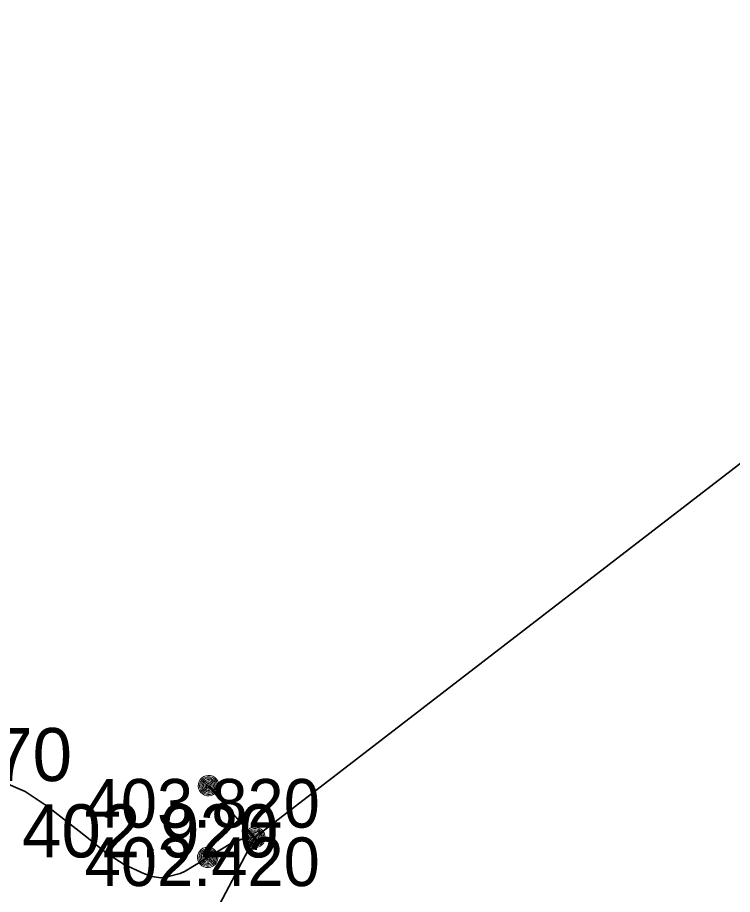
# Model space of a CAD drawing. Extents: x -873619 to -867639, y -1015082 to -1012326.
# Drawn here: x -867971.06 to -867954.89, y -1012799.51 to -1012779.69 of the extents above; entities that cross this region are included whole.
import ezdxf

# ---------------------------------------------------------------- set-up
doc = ezdxf.new("R2010")
doc.units = 0
doc.header["$LTSCALE"] = 0.44
for name, color, linetype, lineweight in [('1', 7, 'Continuous', 13), ('21', 7, 'Continuous', 35), ('23', 7, 'Continuous', 25), ('25', 7, 'Continuous', 13), ('32', 7, 'Continuous', 13)]:
    doc.layers.add(name, color=color, linetype=linetype, lineweight=lineweight)

msp = doc.modelspace()

# ---------------------------------------------------------------- linework, layer by layer
at = {"layer": '1'}
for points in [[(-867966.527, -1012798.672), (-867966.533, -1012798.62), (-867966.55, -1012798.57), (-867966.579, -1012798.526), (-867966.616, -1012798.489), (-867966.661, -1012798.462), (-867966.711, -1012798.445), (-867966.764, -1012798.441), (-867966.816, -1012798.448), (-867966.865, -1012798.467), (-867966.908, -1012798.496), (-867966.944, -1012798.535), (-867966.97, -1012798.58), (-867966.986, -1012798.631), (-867966.989, -1012798.683), (-867966.981, -1012798.735), (-867966.961, -1012798.784), (-867966.93, -1012798.827), (-867966.891, -1012798.861), (-867966.845, -1012798.887), (-867966.794, -1012798.901), (-867966.741, -1012798.903), (-867966.69, -1012798.893), (-867966.642, -1012798.872), (-867966.599, -1012798.841), (-867966.565, -1012798.8), (-867966.541, -1012798.754), (-867966.529, -1012798.703)], [(-867966.557, -1012798.672), (-867966.563, -1012798.623), (-867966.58, -1012798.577), (-867966.608, -1012798.537), (-867966.645, -1012798.505), (-867966.689, -1012798.483), (-867966.737, -1012798.472), (-867966.786, -1012798.472), (-867966.833, -1012798.485), (-867966.876, -1012798.509), (-867966.912, -1012798.542), (-867966.939, -1012798.583), (-867966.955, -1012798.63), (-867966.959, -1012798.679), (-867966.952, -1012798.727), (-867966.933, -1012798.772), (-867966.903, -1012798.812), (-867966.865, -1012798.843), (-867966.821, -1012798.863), (-867966.773, -1012798.873), (-867966.724, -1012798.871), (-867966.677, -1012798.856), (-867966.634, -1012798.831), (-867966.6, -1012798.797), (-867966.574, -1012798.755), (-867966.56, -1012798.708)], [(-867966.587, -1012798.672), (-867966.593, -1012798.627), (-867966.61, -1012798.585), (-867966.638, -1012798.55), (-867966.674, -1012798.523), (-867966.716, -1012798.506), (-867966.761, -1012798.501), (-867966.806, -1012798.507), (-867966.847, -1012798.526), (-867966.882, -1012798.554), (-867966.909, -1012798.591), (-867966.925, -1012798.633), (-867966.929, -1012798.678), (-867966.922, -1012798.723), (-867966.903, -1012798.764), (-867966.874, -1012798.798), (-867966.837, -1012798.824), (-867966.794, -1012798.84), (-867966.749, -1012798.843), (-867966.704, -1012798.835), (-867966.664, -1012798.815), (-867966.63, -1012798.786), (-867966.604, -1012798.748), (-867966.59, -1012798.705)], [(-867966.617, -1012798.672), (-867966.622, -1012798.631), (-867966.64, -1012798.594), (-867966.667, -1012798.563), (-867966.702, -1012798.542), (-867966.742, -1012798.531), (-867966.783, -1012798.533), (-867966.822, -1012798.546), (-867966.856, -1012798.57), (-867966.881, -1012798.602), (-867966.896, -1012798.64), (-867966.899, -1012798.681), (-867966.891, -1012798.721), (-867966.871, -1012798.757), (-867966.842, -1012798.786), (-867966.805, -1012798.805), (-867966.765, -1012798.813), (-867966.724, -1012798.809), (-867966.686, -1012798.794), (-867966.654, -1012798.768), (-867966.631, -1012798.734), (-867966.618, -1012798.695)], [(-867966.647, -1012798.672), (-867966.652, -1012798.636), (-867966.67, -1012798.604), (-867966.696, -1012798.579), (-867966.73, -1012798.564), (-867966.766, -1012798.561), (-867966.801, -1012798.569), (-867966.832, -1012798.589), (-867966.855, -1012798.617), (-867966.868, -1012798.651), (-867966.868, -1012798.688), (-867966.857, -1012798.723), (-867966.836, -1012798.752), (-867966.806, -1012798.773), (-867966.771, -1012798.783), (-867966.734, -1012798.781), (-867966.7, -1012798.767), (-867966.673, -1012798.744), (-867966.654, -1012798.712), (-867966.647, -1012798.677)], [(-867966.677, -1012798.672), (-867966.682, -1012798.641), (-867966.699, -1012798.615), (-867966.725, -1012798.598), (-867966.755, -1012798.591), (-867966.786, -1012798.595), (-867966.813, -1012798.612), (-867966.831, -1012798.636), (-867966.839, -1012798.667), (-867966.835, -1012798.697), (-867966.82, -1012798.725), (-867966.796, -1012798.744), (-867966.766, -1012798.753), (-867966.735, -1012798.75), (-867966.707, -1012798.736), (-867966.687, -1012798.712), (-867966.677, -1012798.683)], [(-867966.707, -1012798.672), (-867966.712, -1012798.648), (-867966.729, -1012798.63), (-867966.752, -1012798.621), (-867966.776, -1012798.624), (-867966.797, -1012798.638), (-867966.808, -1012798.66), (-867966.808, -1012798.685), (-867966.796, -1012798.706), (-867966.776, -1012798.72), (-867966.751, -1012798.723), (-867966.728, -1012798.714), (-867966.712, -1012798.696)], [(-867966.737, -1012798.672), (-867966.742, -1012798.657), (-867966.757, -1012798.651), (-867966.772, -1012798.655), (-867966.779, -1012798.669), (-867966.775, -1012798.684), (-867966.762, -1012798.693), (-867966.747, -1012798.69), (-867966.737, -1012798.678)]]:
    msp.add_lwpolyline(points, close=True, dxfattribs=at)
at = {"layer": '21'}
msp.add_line((-867966.775, -1012797.04), (-867965.676, -1012798.237), dxfattribs=at)
for points in [[(-867965.69, -1012798.22), (-867951.608, -1012787.375), (-867932.702, -1012789.133), (-867922.911, -1012779.695)], [(-867971.426, -1012796.948), (-867970.889, -1012797.18), (-867970.387, -1012797.515), (-867969.494, -1012798.212), (-867969.047, -1012798.575), (-867968.649, -1012798.834), (-867968.188, -1012799.044), (-867968.014, -1012799.106), (-867967.827, -1012799.134), (-867967.643, -1012799.106), (-867967.379, -1012799.036), (-867967.269, -1012798.98), (-867966.197, -1012798.333), (-867965.963, -1012798.255), (-867965.69, -1012798.22)], [(-868020.287, -1012856.898), (-867997.903, -1012847.584), (-867988.318, -1012833.474), (-867978.718, -1012822.899), (-867965.69, -1012798.22), (-867965.665, -1012798.299)]]:
    msp.add_lwpolyline(points, dxfattribs=at)
at = {"layer": '23'}
msp.add_line((-867966.74, -1012797.05), (-867965.665, -1012798.299), dxfattribs=at)
at = {"layer": '25'}
for points in [[(-867966.509, -1012797.05), (-867966.515, -1012796.998), (-867966.532, -1012796.948), (-867966.561, -1012796.904), (-867966.598, -1012796.867), (-867966.643, -1012796.84), (-867966.693, -1012796.823), (-867966.746, -1012796.819), (-867966.798, -1012796.826), (-867966.847, -1012796.845), (-867966.89, -1012796.874), (-867966.926, -1012796.913), (-867966.952, -1012796.958), (-867966.968, -1012797.009), (-867966.971, -1012797.061), (-867966.963, -1012797.113), (-867966.943, -1012797.162), (-867966.912, -1012797.205), (-867966.873, -1012797.239), (-867966.827, -1012797.265), (-867966.776, -1012797.279), (-867966.723, -1012797.281), (-867966.672, -1012797.271), (-867966.624, -1012797.25), (-867966.581, -1012797.219), (-867966.547, -1012797.178), (-867966.523, -1012797.132), (-867966.511, -1012797.081)], [(-867966.539, -1012797.05), (-867966.545, -1012797.001), (-867966.562, -1012796.955), (-867966.59, -1012796.915), (-867966.627, -1012796.883), (-867966.671, -1012796.861), (-867966.719, -1012796.85), (-867966.768, -1012796.85), (-867966.815, -1012796.863), (-867966.858, -1012796.887), (-867966.894, -1012796.92), (-867966.921, -1012796.961), (-867966.937, -1012797.008), (-867966.941, -1012797.057), (-867966.934, -1012797.105), (-867966.915, -1012797.15), (-867966.885, -1012797.19), (-867966.847, -1012797.221), (-867966.803, -1012797.241), (-867966.755, -1012797.251), (-867966.706, -1012797.249), (-867966.659, -1012797.234), (-867966.616, -1012797.209), (-867966.581, -1012797.175), (-867966.556, -1012797.133), (-867966.542, -1012797.086)], [(-867966.569, -1012797.05), (-867966.575, -1012797.005), (-867966.592, -1012796.963), (-867966.62, -1012796.928), (-867966.656, -1012796.901), (-867966.698, -1012796.884), (-867966.743, -1012796.879), (-867966.788, -1012796.885), (-867966.829, -1012796.904), (-867966.864, -1012796.932), (-867966.891, -1012796.969), (-867966.907, -1012797.011), (-867966.911, -1012797.056), (-867966.904, -1012797.101), (-867966.885, -1012797.142), (-867966.856, -1012797.176), (-867966.819, -1012797.202), (-867966.776, -1012797.218), (-867966.731, -1012797.221), (-867966.686, -1012797.213), (-867966.646, -1012797.193), (-867966.612, -1012797.164), (-867966.586, -1012797.126), (-867966.572, -1012797.083)], [(-867966.599, -1012797.05), (-867966.603, -1012797.009), (-867966.622, -1012796.972), (-867966.649, -1012796.941), (-867966.684, -1012796.92), (-867966.724, -1012796.909), (-867966.765, -1012796.911), (-867966.804, -1012796.924), (-867966.838, -1012796.948), (-867966.863, -1012796.98), (-867966.878, -1012797.018), (-867966.88, -1012797.059), (-867966.873, -1012797.099), (-867966.853, -1012797.135), (-867966.824, -1012797.164), (-867966.787, -1012797.183), (-867966.747, -1012797.191), (-867966.706, -1012797.187), (-867966.668, -1012797.172), (-867966.636, -1012797.146), (-867966.613, -1012797.112), (-867966.6, -1012797.073)], [(-867966.629, -1012797.05), (-867966.634, -1012797.014), (-867966.652, -1012796.982), (-867966.678, -1012796.957), (-867966.712, -1012796.942), (-867966.748, -1012796.939), (-867966.782, -1012796.947), (-867966.814, -1012796.967), (-867966.837, -1012796.995), (-867966.85, -1012797.029), (-867966.85, -1012797.066), (-867966.839, -1012797.101), (-867966.818, -1012797.13), (-867966.788, -1012797.151), (-867966.753, -1012797.161), (-867966.716, -1012797.159), (-867966.682, -1012797.145), (-867966.655, -1012797.122), (-867966.636, -1012797.09), (-867966.629, -1012797.055)], [(-867966.659, -1012797.05), (-867966.664, -1012797.019), (-867966.681, -1012796.993), (-867966.706, -1012796.976), (-867966.737, -1012796.969), (-867966.768, -1012796.973), (-867966.795, -1012796.99), (-867966.813, -1012797.014), (-867966.821, -1012797.045), (-867966.817, -1012797.075), (-867966.802, -1012797.103), (-867966.777, -1012797.122), (-867966.748, -1012797.131), (-867966.717, -1012797.128), (-867966.689, -1012797.114), (-867966.669, -1012797.09), (-867966.659, -1012797.061)], [(-867966.689, -1012797.05), (-867966.694, -1012797.026), (-867966.711, -1012797.008), (-867966.733, -1012796.999), (-867966.758, -1012797.002), (-867966.779, -1012797.016), (-867966.79, -1012797.038), (-867966.79, -1012797.063), (-867966.777, -1012797.084), (-867966.758, -1012797.098), (-867966.733, -1012797.101), (-867966.71, -1012797.092), (-867966.694, -1012797.074)], [(-867966.719, -1012797.05), (-867966.724, -1012797.035), (-867966.739, -1012797.029), (-867966.754, -1012797.033), (-867966.761, -1012797.047), (-867966.757, -1012797.062), (-867966.744, -1012797.071), (-867966.728, -1012797.068), (-867966.719, -1012797.056)]]:
    msp.add_lwpolyline(points, close=True, dxfattribs=at)
at = {"layer": '32'}
for points in [[(-867965.458, -1012798.22), (-867965.465, -1012798.168), (-867965.482, -1012798.118), (-867965.511, -1012798.074), (-867965.548, -1012798.037), (-867965.593, -1012798.01), (-867965.642, -1012797.993), (-867965.696, -1012797.989), (-867965.747, -1012797.996), (-867965.796, -1012798.015), (-867965.84, -1012798.044), (-867965.875, -1012798.083), (-867965.902, -1012798.128), (-867965.918, -1012798.179), (-867965.921, -1012798.231), (-867965.913, -1012798.283), (-867965.892, -1012798.332), (-867965.862, -1012798.375), (-867965.823, -1012798.409), (-867965.777, -1012798.435), (-867965.725, -1012798.449), (-867965.673, -1012798.451), (-867965.622, -1012798.441), (-867965.573, -1012798.42), (-867965.531, -1012798.389), (-867965.497, -1012798.348), (-867965.473, -1012798.302), (-867965.46, -1012798.251)], [(-867965.489, -1012798.22), (-867965.495, -1012798.171), (-867965.512, -1012798.125), (-867965.539, -1012798.085), (-867965.576, -1012798.053), (-867965.62, -1012798.031), (-867965.669, -1012798.02), (-867965.718, -1012798.02), (-867965.764, -1012798.033), (-867965.808, -1012798.057), (-867965.843, -1012798.09), (-867965.87, -1012798.131), (-867965.887, -1012798.178), (-867965.891, -1012798.227), (-867965.884, -1012798.275), (-867965.865, -1012798.32), (-867965.835, -1012798.36), (-867965.796, -1012798.391), (-867965.752, -1012798.411), (-867965.705, -1012798.421), (-867965.656, -1012798.419), (-867965.608, -1012798.404), (-867965.566, -1012798.379), (-867965.531, -1012798.345), (-867965.505, -1012798.303), (-867965.492, -1012798.256)], [(-867965.519, -1012798.22), (-867965.524, -1012798.175), (-867965.541, -1012798.133), (-867965.57, -1012798.098), (-867965.605, -1012798.071), (-867965.647, -1012798.054), (-867965.693, -1012798.049), (-867965.737, -1012798.055), (-867965.779, -1012798.074), (-867965.813, -1012798.102), (-867965.84, -1012798.139), (-867965.857, -1012798.181), (-867965.86, -1012798.226), (-867965.853, -1012798.271), (-867965.835, -1012798.312), (-867965.806, -1012798.346), (-867965.769, -1012798.372), (-867965.725, -1012798.388), (-867965.681, -1012798.391), (-867965.636, -1012798.383), (-867965.595, -1012798.363), (-867965.561, -1012798.334), (-867965.536, -1012798.296), (-867965.522, -1012798.253)], [(-867965.549, -1012798.22), (-867965.553, -1012798.179), (-867965.571, -1012798.142), (-867965.598, -1012798.111), (-867965.634, -1012798.09), (-867965.674, -1012798.079), (-867965.715, -1012798.081), (-867965.754, -1012798.094), (-867965.788, -1012798.118), (-867965.813, -1012798.15), (-867965.828, -1012798.188), (-867965.83, -1012798.229), (-867965.823, -1012798.269), (-867965.803, -1012798.305), (-867965.774, -1012798.334), (-867965.737, -1012798.353), (-867965.696, -1012798.361), (-867965.656, -1012798.357), (-867965.617, -1012798.342), (-867965.585, -1012798.316), (-867965.563, -1012798.282), (-867965.549, -1012798.243)], [(-867965.578, -1012798.22), (-867965.583, -1012798.184), (-867965.602, -1012798.152), (-867965.627, -1012798.127), (-867965.661, -1012798.112), (-867965.698, -1012798.109), (-867965.732, -1012798.117), (-867965.764, -1012798.137), (-867965.786, -1012798.165), (-867965.799, -1012798.199), (-867965.799, -1012798.236), (-867965.789, -1012798.271), (-867965.767, -1012798.3), (-867965.737, -1012798.321), (-867965.703, -1012798.331), (-867965.666, -1012798.329), (-867965.632, -1012798.315), (-867965.605, -1012798.292), (-867965.585, -1012798.26), (-867965.578, -1012798.225)], [(-867965.608, -1012798.22), (-867965.614, -1012798.189), (-867965.63, -1012798.163), (-867965.656, -1012798.146), (-867965.686, -1012798.139), (-867965.718, -1012798.143), (-867965.745, -1012798.16), (-867965.762, -1012798.184), (-867965.771, -1012798.215), (-867965.767, -1012798.245), (-867965.752, -1012798.273), (-867965.727, -1012798.292), (-867965.698, -1012798.301), (-867965.666, -1012798.298), (-867965.639, -1012798.284), (-867965.619, -1012798.26), (-867965.608, -1012798.231)], [(-867965.639, -1012798.22), (-867965.644, -1012798.196), (-867965.661, -1012798.178), (-867965.683, -1012798.169), (-867965.708, -1012798.172), (-867965.728, -1012798.186), (-867965.74, -1012798.208), (-867965.74, -1012798.233), (-867965.727, -1012798.254), (-867965.708, -1012798.268), (-867965.683, -1012798.271), (-867965.659, -1012798.262), (-867965.644, -1012798.244)], [(-867965.669, -1012798.22), (-867965.674, -1012798.205), (-867965.688, -1012798.199), (-867965.703, -1012798.203), (-867965.71, -1012798.217), (-867965.706, -1012798.232), (-867965.693, -1012798.241), (-867965.678, -1012798.238), (-867965.669, -1012798.226)]]:
    msp.add_lwpolyline(points, close=True, dxfattribs=at)

# ---------------------------------------------------------------- texts
at = {"layer": '1'}
for s, height, p in [('402.970 ', 1.2, (-867975.626, -1012796.948)), ('403.820 ', 1.1, (-867969.54, -1012798)), ('402.920 ', 1.2, (-867970.958, -1012798.672)), ('402.420 ', 1.1, (-867969.54, -1012799.32))]:
    msp.add_text(s, height=height, dxfattribs=at).set_placement(p)

doc.saveas('drawing.dxf')
